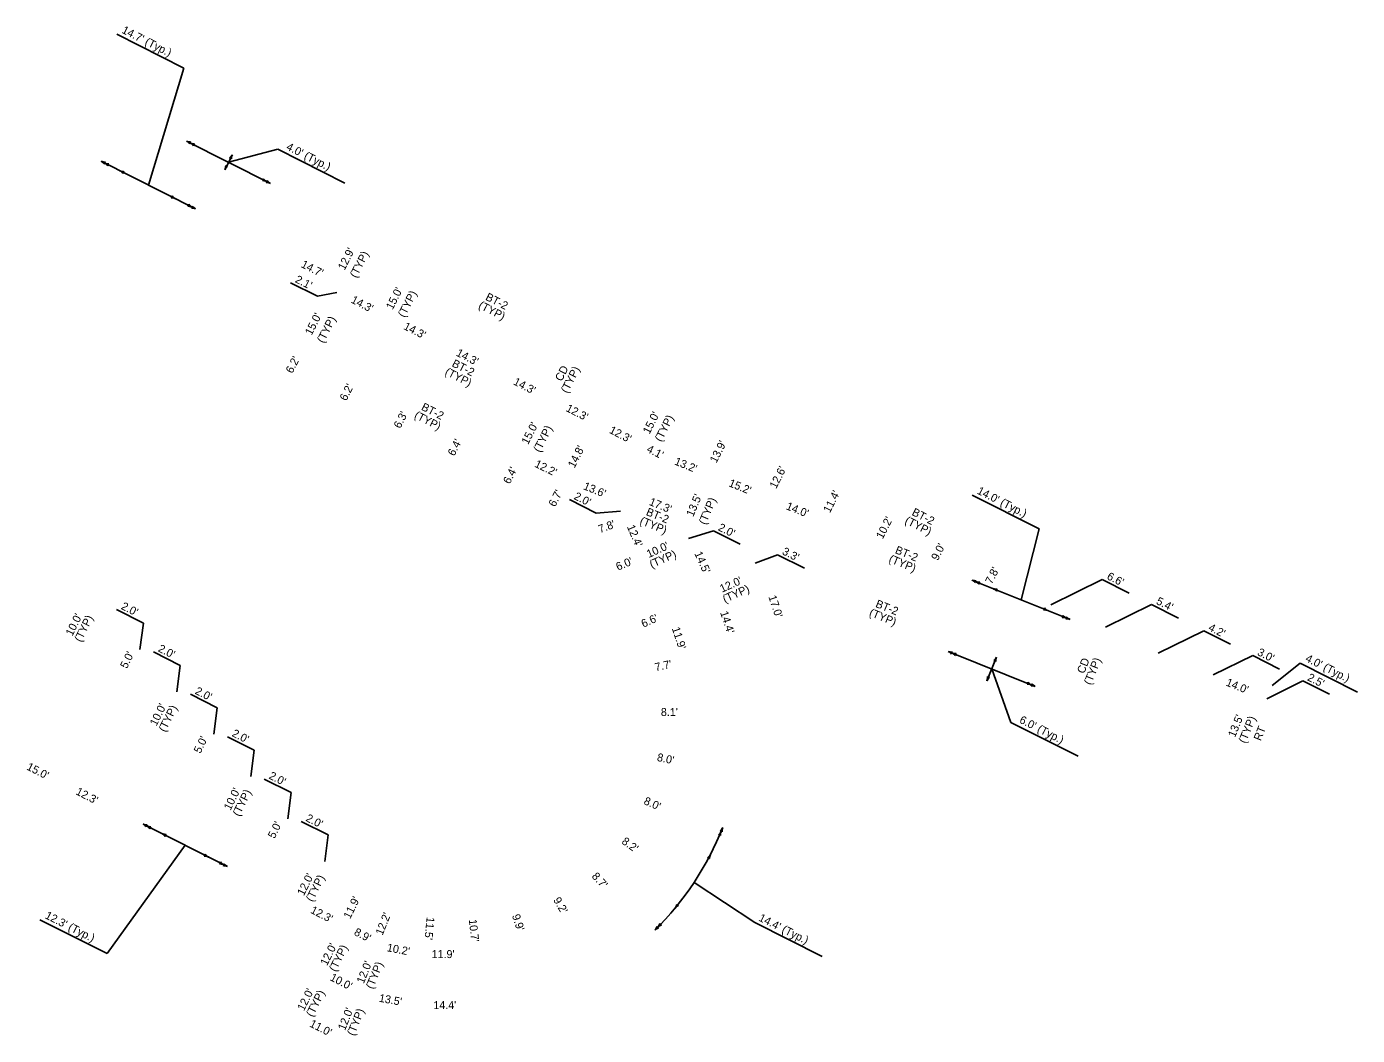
# Model space of a CAD drawing. Extents: x 15558215 to 15558792, y 8787373 to 8787891.
# Drawn here: x 15558477.5 to 15558791.7, y 8787532.3 to 8787770.4 of the extents above; entities that cross this region are included whole.
import ezdxf

# ---------------------------------------------------------------- set-up
doc = ezdxf.new("R2010")
doc.units = 0
doc.layers.add('Draft_Plan_Labels', color=7, linetype='Continuous')
doc.layers.add('Text', color=7, linetype='Continuous')

msp = doc.modelspace()

# ---------------------------------------------------------------- linework, layer by layer
at = {"layer": 'Draft_Plan_Labels'}
for p, q in [((15558515.26, 8787743.4), (15558515.69, 8787743.18)), ((15558515.26, 8787743.4), (15558516.11, 8787742.97)), ((15558516.11, 8787742.97), (15558516.55, 8787742.75)), ((15558516.11, 8787742.97), (15558516.97, 8787742.54)), ((15558526.06, 8787740.19), (15558525.62, 8787739.34)), ((15558526.06, 8787740.19), (15558525.84, 8787739.76)), ((15558495.06, 8787738.66), (15558495.49, 8787738.44)), ((15558495.06, 8787738.66), (15558495.92, 8787738.23)), ((15558495.92, 8787738.23), (15558496.35, 8787738.01)), ((15558495.92, 8787738.23), (15558496.78, 8787737.79)), ((15558524.26, 8787736.62), (15558524.69, 8787737.48)), ((15558524.26, 8787736.62), (15558524.47, 8787737.05)), ((15558499.53, 8787736.41), (15558499.96, 8787736.19)), ((15558499.53, 8787736.41), (15558500.38, 8787735.97)), ((15558534.2, 8787733.85), (15558533.34, 8787734.28)), ((15558534.2, 8787733.85), (15558533.77, 8787734.06)), ((15558535.06, 8787733.41), (15558534.2, 8787733.85)), ((15558535.06, 8787733.41), (15558534.62, 8787733.63)), ((15558512.61, 8787729.81), (15558511.75, 8787730.24)), ((15558512.61, 8787729.81), (15558512.18, 8787730.02)), ((15558516.52, 8787727.83), (15558515.67, 8787728.26)), ((15558516.52, 8787727.83), (15558516.09, 8787728.05)), ((15558517.38, 8787727.4), (15558516.52, 8787727.83)), ((15558517.38, 8787727.4), (15558516.95, 8787727.62)), ((15558700.65, 8787639.79), (15558701.1, 8787639.61)), ((15558700.65, 8787639.79), (15558701.54, 8787639.43)), ((15558701.54, 8787639.43), (15558701.99, 8787639.25)), ((15558701.54, 8787639.43), (15558702.44, 8787639.08)), ((15558705.63, 8787637.8), (15558706.08, 8787637.62)), ((15558705.63, 8787637.8), (15558706.53, 8787637.44)), ((15558718.59, 8787632.61), (15558717.69, 8787632.96)), ((15558718.59, 8787632.61), (15558718.14, 8787632.79)), ((15558722.97, 8787630.85), (15558722.07, 8787631.21)), ((15558722.97, 8787630.85), (15558722.52, 8787631.03)), ((15558723.86, 8787630.49), (15558722.97, 8787630.85)), ((15558723.86, 8787630.49), (15558723.41, 8787630.67)), ((15558695.04, 8787622.96), (15558695.49, 8787622.78)), ((15558695.04, 8787622.96), (15558695.93, 8787622.6)), ((15558695.93, 8787622.6), (15558696.38, 8787622.42)), ((15558695.93, 8787622.6), (15558696.83, 8787622.24)), ((15558706.45, 8787621.62), (15558706.09, 8787620.72)), ((15558706.45, 8787621.62), (15558706.27, 8787621.17)), ((15558704.22, 8787616.05), (15558704.58, 8787616.94)), ((15558704.22, 8787616.05), (15558704.4, 8787616.5)), ((15558714.74, 8787615.06), (15558713.84, 8787615.42)), ((15558714.74, 8787615.06), (15558714.29, 8787615.24)), ((15558715.63, 8787614.71), (15558714.74, 8787615.06)), ((15558715.63, 8787614.71), (15558715.18, 8787614.89)), ((15558504.97, 8787582.22), (15558505.4, 8787582)), ((15558504.97, 8787582.22), (15558505.83, 8787581.79)), ((15558505.83, 8787581.79), (15558506.26, 8787581.57)), ((15558505.83, 8787581.79), (15558506.68, 8787581.35)), ((15558509.43, 8787579.97), (15558509.86, 8787579.75)), ((15558509.43, 8787579.97), (15558510.29, 8787579.54)), ((15558641.47, 8787580.52), (15558641.1, 8787579.64)), ((15558641.47, 8787580.52), (15558641.28, 8787580.08)), ((15558641.83, 8787581.42), (15558641.47, 8787580.52)), ((15558641.83, 8787581.42), (15558641.65, 8787580.97)), ((15558520.41, 8787574.43), (15558519.55, 8787574.86)), ((15558520.41, 8787574.43), (15558519.98, 8787574.65)), ((15558638.94, 8787575.04), (15558638.49, 8787574.19)), ((15558638.94, 8787575.04), (15558638.71, 8787574.61)), ((15558524.01, 8787572.61), (15558523.16, 8787573.04)), ((15558524.01, 8787572.61), (15558523.58, 8787572.83)), ((15558524.87, 8787572.18), (15558524.01, 8787572.61)), ((15558524.87, 8787572.18), (15558524.44, 8787572.4)), ((15558630.52, 8787562.31), (15558631.13, 8787563.05)), ((15558630.52, 8787562.31), (15558630.83, 8787562.69)), ((15558625.79, 8787557.16), (15558626.47, 8787557.83)), ((15558625.79, 8787557.16), (15558626.13, 8787557.5)), ((15558626.47, 8787557.83), (15558627.14, 8787558.52)), ((15558626.47, 8787557.83), (15558626.81, 8787558.18))]:
    msp.add_line(p, q, dxfattribs=at)
for centre, radius, start, end in [((15558514.3, 8787741.51), 2.12, 35.1558, 63.2283), ((15558516.21, 8787745.3), 2.12, 243.2283, 271.3008), ((15558516.85, 8787742.6), 0.821, 135.495, 170.9617), ((15558515.16, 8787741.07), 2.12, 35.1558, 63.2283), ((15558517.07, 8787744.87), 2.12, 243.2283, 271.3008), ((15558517.7, 8787742.17), 0.821, 135.495, 170.9617), ((15558524.16, 8787741.15), 2.12, 305.1559, 333.2283), ((15558527.95, 8787739.24), 2.12, 153.2283, 181.3008), ((15558496.02, 8787740.56), 2.12, 243.2283, 271.3008), ((15558494.1, 8787736.76), 2.12, 35.1558, 63.2283), ((15558496.65, 8787737.86), 0.821, 135.495, 170.9617), ((15558496.88, 8787740.12), 2.12, 243.2283, 271.3008), ((15558494.96, 8787736.33), 2.12, 35.1558, 63.2283), ((15558497.51, 8787737.42), 0.821, 135.495, 170.9617), ((15558522.36, 8787737.58), 2.12, 333.2283, 1.3008), ((15558526.15, 8787735.66), 2.12, 125.1558, 153.2283), ((15558525.06, 8787738.21), 0.821, 225.495, 260.9617), ((15558525.25, 8787738.6), 0.821, 45.495, 80.9617), ((15558500.48, 8787738.3), 2.12, 243.2283, 271.3008), ((15558498.57, 8787734.51), 2.12, 35.1558, 63.2283), ((15558501.12, 8787735.61), 0.821, 135.495, 170.9617), ((15558532.61, 8787734.65), 0.821, 315.495, 350.9617), ((15558533.24, 8787731.95), 2.12, 63.2283, 91.3008), ((15558535.16, 8787735.74), 2.12, 215.1559, 243.2283), ((15558533.47, 8787734.22), 0.821, 315.495, 350.9617), ((15558534.1, 8787731.52), 2.12, 63.2283, 91.3008), ((15558536.01, 8787735.31), 2.12, 215.1559, 243.2283), ((15558511.02, 8787730.61), 0.821, 315.495, 350.9617), ((15558513.57, 8787731.7), 2.12, 215.1559, 243.2283), ((15558511.65, 8787727.91), 2.12, 63.2283, 91.3008), ((15558514.93, 8787728.63), 0.821, 315.495, 350.9617), ((15558515.57, 8787725.93), 2.12, 63.2283, 91.3008), ((15558517.48, 8787729.73), 2.12, 215.1559, 243.2283), ((15558515.79, 8787728.2), 0.821, 315.495, 350.9617), ((15558516.42, 8787725.5), 2.12, 63.2283, 91.3008), ((15558518.34, 8787729.3), 2.12, 215.1559, 243.2283), ((15558701.44, 8787641.76), 2.12, 248.1655, 276.238), ((15558699.86, 8787637.82), 2.12, 40.0931, 68.1655), ((15558702.31, 8787639.13), 0.821, 140.4322, 175.8989), ((15558702.33, 8787641.41), 2.12, 248.1655, 276.238), ((15558700.75, 8787637.46), 2.12, 40.0931, 68.1655), ((15558703.2, 8787638.77), 0.821, 140.4322, 175.8989), ((15558706.42, 8787639.77), 2.12, 248.1655, 276.238), ((15558704.84, 8787635.82), 2.12, 40.0931, 68.1655), ((15558707.29, 8787637.13), 0.821, 140.4322, 175.8989), ((15558716.93, 8787633.27), 0.821, 320.4322, 355.8989), ((15558719.38, 8787634.58), 2.12, 220.0931, 248.1655), ((15558717.8, 8787630.63), 2.12, 68.1655, 96.238), ((15558721.31, 8787631.51), 0.821, 320.4322, 355.8989), ((15558722.18, 8787628.88), 2.12, 68.1655, 96.238), ((15558723.76, 8787632.82), 2.12, 220.0931, 248.1655), ((15558722.2, 8787631.16), 0.821, 320.4322, 355.8989), ((15558723.07, 8787628.52), 2.12, 68.1655, 96.238), ((15558724.65, 8787632.47), 2.12, 220.0931, 248.1655), ((15558694.25, 8787620.98), 2.12, 40.0931, 68.1655), ((15558695.83, 8787624.93), 2.12, 248.1655, 276.238), ((15558696.7, 8787622.29), 0.821, 140.4322, 175.8989), ((15558695.14, 8787620.63), 2.12, 40.0931, 68.1655), ((15558696.72, 8787624.57), 2.12, 248.1655, 276.238), ((15558697.59, 8787621.94), 0.821, 140.4322, 175.8989), ((15558704.48, 8787622.41), 2.12, 310.0931, 338.1655), ((15558705.79, 8787619.96), 0.821, 50.4322, 85.8989), ((15558708.42, 8787620.83), 2.12, 158.1655, 186.238), ((15558702.25, 8787616.84), 2.12, 338.1655, 6.238), ((15558704.88, 8787617.7), 0.821, 230.4322, 265.8989), ((15558706.19, 8787615.26), 2.12, 130.0931, 158.1655), ((15558713.08, 8787615.73), 0.821, 320.4322, 355.8989), ((15558713.95, 8787613.09), 2.12, 68.1655, 96.238), ((15558715.53, 8787617.04), 2.12, 220.0931, 248.1655), ((15558713.97, 8787615.37), 0.821, 320.4322, 355.8989), ((15558714.84, 8787612.73), 2.12, 68.1655, 96.238), ((15558716.42, 8787616.68), 2.12, 220.0931, 248.1655), ((15558505.92, 8787584.12), 2.12, 243.2283, 271.3008), ((15558504.01, 8787580.32), 2.12, 35.1558, 63.2283), ((15558506.56, 8787581.42), 0.821, 135.495, 170.9617), ((15558506.78, 8787583.68), 2.12, 243.2283, 271.3008), ((15558504.87, 8787579.89), 2.12, 35.1558, 63.2283), ((15558507.42, 8787580.98), 0.821, 135.495, 170.9617), ((15558510.39, 8787581.87), 2.12, 243.2283, 271.3008), ((15558508.47, 8787578.07), 2.12, 35.1558, 63.2283), ((15558511.02, 8787579.17), 0.821, 135.495, 170.9617), ((15558639.51, 8787581.34), 2.12, 309.2143, 337.2868), ((15558640.78, 8787578.88), 0.821, 49.5535, 85.0202), ((15558639.86, 8787582.21), 2.12, 309.997, 338.0695), ((15558641.16, 8787579.76), 0.821, 50.3361, 85.8029), ((15558643.43, 8787579.7), 2.12, 157.2868, 185.3593), ((15558643.8, 8787580.62), 2.12, 158.0695, 186.142), ((15558518.82, 8787575.23), 0.821, 315.495, 350.9617), ((15558519.45, 8787572.53), 2.12, 63.2283, 91.3008), ((15558521.37, 8787576.33), 2.12, 215.1559, 243.2283), ((15558522.42, 8787573.41), 0.821, 315.495, 350.9617), ((15558524.97, 8787574.51), 2.12, 215.1559, 243.2283), ((15558637.05, 8787576.03), 2.12, 304.2959, 332.3684), ((15558638.11, 8787573.46), 0.821, 44.6351, 80.1018), ((15558640.82, 8787574.06), 2.12, 152.3684, 180.4409), ((15558523.06, 8787570.71), 2.12, 63.2283, 91.3008), ((15558523.28, 8787572.98), 0.821, 315.495, 350.9617), ((15558523.92, 8787570.28), 2.12, 63.2283, 91.3008), ((15558525.83, 8787574.08), 2.12, 215.1559, 243.2283), ((15558628.88, 8787563.66), 2.12, 320.6974, 348.7699), ((15558632.16, 8787560.96), 2.12, 112.6249, 140.6974), ((15558631.65, 8787563.69), 0.821, 212.964, 248.4307), ((15558624.29, 8787558.66), 2.12, 314.9963, 343.0688), ((15558627.29, 8787555.65), 2.12, 106.9238, 134.9963), ((15558627.05, 8787558.42), 0.821, 207.2629, 242.7296), ((15558624.95, 8787559.32), 2.12, 315.779, 343.8515), ((15558627.99, 8787556.35), 2.12, 107.7065, 135.779), ((15558627.71, 8787559.11), 0.821, 208.0456, 243.5123)]:
    msp.add_arc(centre, radius, start, end, dxfattribs=at)
at = {"layer": 'Text'}
for p, q in [((15558498.75, 8787768.62), (15558514.61, 8787760.62)), ((15558506.22, 8787733.03), (15558514.61, 8787760.62)), ((15558535.06, 8787733.41), (15558515.26, 8787743.4)), ((15558526.06, 8787740.19), (15558524.26, 8787736.62)), ((15558525.16, 8787738.41), (15558536.77, 8787741.48)), ((15558536.77, 8787741.48), (15558552.63, 8787733.48)), ((15558495.06, 8787738.66), (15558517.38, 8787727.4)), ((15558546.13, 8787706.77), (15558539.81, 8787709.96)), ((15558550.7, 8787707.69), (15558546.13, 8787706.77)), ((15558611.95, 8787655.62), (15558605.63, 8787658.81)), ((15558700.68, 8787659.87), (15558716.54, 8787651.87)), ((15558617.72, 8787656.06), (15558611.95, 8787655.62)), ((15558712.26, 8787635.14), (15558716.54, 8787651.87)), ((15558633.74, 8787649.58), (15558639.66, 8787651.43)), ((15558645.98, 8787648.24), (15558639.66, 8787651.43)), ((15558649.46, 8787643.78), (15558654.79, 8787645.77)), ((15558661.11, 8787642.58), (15558654.79, 8787645.77)), ((15558700.65, 8787639.79), (15558723.86, 8787630.49)), ((15558719.26, 8787633.94), (15558731.44, 8787639.9)), ((15558737.76, 8787636.72), (15558731.44, 8787639.9)), ((15558505.04, 8787629.66), (15558498.72, 8787632.85)), ((15558732.18, 8787628.69), (15558743.09, 8787634.03)), ((15558749.41, 8787630.84), (15558743.09, 8787634.03)), ((15558504.25, 8787623.42), (15558505.04, 8787629.66)), ((15558744.65, 8787622.55), (15558755.41, 8787627.81)), ((15558761.73, 8787624.63), (15558755.41, 8787627.81)), ((15558513.76, 8787619.65), (15558507.44, 8787622.84)), ((15558715.63, 8787614.71), (15558695.04, 8787622.96)), ((15558706.45, 8787621.62), (15558704.22, 8787616.05)), ((15558757.59, 8787617.4), (15558766.96, 8787621.98)), ((15558773.28, 8787618.8), (15558766.96, 8787621.98)), ((15558512.97, 8787613.42), (15558513.76, 8787619.65)), ((15558705.34, 8787618.83), (15558709.87, 8787606.2)), ((15558771.52, 8787614.94), (15558778.17, 8787620.17)), ((15558791.67, 8787613.36), (15558778.17, 8787620.17)), ((15558770.25, 8787611.77), (15558778.78, 8787616.02)), ((15558785.1, 8787612.84), (15558778.78, 8787616.02)), ((15558522.48, 8787609.65), (15558516.16, 8787612.84)), ((15558521.69, 8787603.41), (15558522.48, 8787609.65)), ((15558709.87, 8787606.2), (15558725.73, 8787598.2)), ((15558531.2, 8787599.64), (15558524.88, 8787602.83)), ((15558530.41, 8787593.41), (15558531.2, 8787599.64)), ((15558539.92, 8787589.64), (15558533.6, 8787592.83)), ((15558539.13, 8787583.41), (15558539.92, 8787589.64)), ((15558548.64, 8787579.64), (15558542.33, 8787582.82)), ((15558504.97, 8787582.22), (15558524.87, 8787572.18)), ((15558547.86, 8787573.4), (15558548.64, 8787579.64)), ((15558514.92, 8787577.2), (15558496.49, 8787551.64)), ((15558635.07, 8787568.45), (15558649.44, 8787558.95)), ((15558480.63, 8787559.64), (15558496.49, 8787551.64)), ((15558665.3, 8787550.95), (15558649.44, 8787558.95))]:
    msp.add_line(p, q, dxfattribs=at)
msp.add_arc((15558576.39, 8787607.24), 70.35, 314.6039, 338.4617, dxfattribs=at)

# ---------------------------------------------------------------- texts
for s, height, rotation, p in [("14.7' (Typ.)", 1.8898, 333.0592, (15558499.79, 8787769.03)), ("4.0' (Typ.)", 1.8898, 333.0592, (15558538.62, 8787741.48)), ("12.9'", 1.89, 63.0592, (15558552.54, 8787712.79)), ("14.7'", 1.89, 332.9068, (15558542.11, 8787713.74)), ('(TYP)', 1.89, 63.0592, (15558555.36, 8787710.96)), ("2.1'", 1.89, 333.0592, (15558540.72, 8787710.16)), ("15.0'", 1.89, 63.0592, (15558563.88, 8787703.46)), ("14.3'", 1.89, 332.9068, (15558553.9, 8787705.36)), ('(TYP)', 1.89, 63.0592, (15558566.7, 8787701.63)), ('(TYP)', 1.89, 332.9068, (15558583.99, 8787704.07)), ('BT-2', 1.89, 332.9068, (15558585.65, 8787706.02)), ("15.0'", 1.89, 63.0592, (15558544.76, 8787697.42)), ('(TYP)', 1.89, 63.0592, (15558547.58, 8787695.59)), ("14.3'", 1.89, 332.9068, (15558566.31, 8787699.1)), ("6.2'", 1.89, 63.0592, (15558540.22, 8787688.43)), ("14.3'", 1.89, 332.9068, (15558578.73, 8787692.84)), ('(TYP)', 1.89, 332.9068, (15558576.07, 8787688.37)), ('BT-2', 1.89, 332.9068, (15558577.73, 8787690.32)), ('CD', 1.89, 62.7464, (15558603.81, 8787686.55)), ('(TYP)', 1.89, 62.7464, (15558605.17, 8787683.75)), ("6.2'", 1.89, 63.0592, (15558552.95, 8787681.94)), ("14.3'", 1.89, 332.9068, (15558592.23, 8787686.03)), ('BT-2', 1.89, 332.9068, (15558570.49, 8787680.06)), ("12.3'", 1.89, 332.9068, (15558604.64, 8787679.76)), ("6.3'", 1.89, 63.0592, (15558565.7, 8787675.43)), ('(TYP)', 1.89, 332.9068, (15558568.82, 8787678.11)), ("15.0'", 1.89, 63.0592, (15558595.87, 8787671.63)), ("15.0'", 1.89, 63.0592, (15558624.52, 8787674.11)), ('(TYP)', 1.89, 63.0592, (15558627.34, 8787672.28)), ('(TYP)', 1.89, 63.0592, (15558598.69, 8787669.8)), ("12.3'", 1.89, 332.9068, (15558614.87, 8787674.6)), ("6.4'", 1.89, 63.0592, (15558578.46, 8787668.92)), ("14.8'", 1.89, 63.0592, (15558606.83, 8787666.11)), ("4.1'", 1.89, 332.9068, (15558623.7, 8787670.14)), ("13.9'", 1.89, 63.0592, (15558640.33, 8787667.28)), ("12.2'", 1.89, 334.1194, (15558597.24, 8787666.6)), ("13.2'", 1.89, 338.1655, (15558630.28, 8787667.11)), ("6.4'", 1.89, 63.0592, (15558591.54, 8787662.32)), ("12.6'", 1.89, 63.0592, (15558654.45, 8787661.22)), ("6.7'", 1.89, 63.0592, (15558602.25, 8787656.92)), ("13.6'", 1.89, 337.7392, (15558608.76, 8787661.28)), ("15.2'", 1.89, 338.1655, (15558643.08, 8787661.98)), ("11.4'", 1.89, 63.0592, (15558667.13, 8787655.51)), ("14.0' (Typ.)", 1.8898, 333.0592, (15558701.72, 8787660.28)), ("2.0'", 1.89, 333.0592, (15558606.54, 8787659)), ("17.3'", 1.89, 337.844, (15558624.29, 8787657.58)), ("13.5'", 1.89, 67.2802, (15558634.86, 8787654.61)), ('(TYP)', 1.89, 67.2802, (15558637.8, 8787652.72)), ("14.0'", 1.89, 338.1655, (15558656.63, 8787656.55)), ('BT-2', 1.89, 337.844, (15558623.57, 8787655.19)), ("10.2'", 1.89, 63.0592, (15558679.59, 8787649.34)), ('(TYP)', 1.89, 332.9068, (15558684.65, 8787653.28)), ('BT-2', 1.89, 332.9068, (15558686.32, 8787655.23)), ("7.8'", 1.89, 20.4831, (15558612.86, 8787650.85)), ("12.4'", 1.89, 293.0649, (15558619.17, 8787652.39)), ('(TYP)', 1.89, 337.844, (15558622.08, 8787653.1)), ("2.0'", 1.89, 333.0592, (15558640.57, 8787651.63)), ("10.0'", 1.89, 24.1758, (15558624.37, 8787644.99)), ("9.0'", 1.89, 63.0592, (15558692.61, 8787644.27)), ('(TYP)', 1.89, 24.1758, (15558625.06, 8787642.56)), ("14.5'", 1.89, 294.176, (15558635.1, 8787646.07)), ("3.3'", 1.89, 333.0592, (15558655.7, 8787645.97)), ('(TYP)', 1.89, 337.844, (15558680.88, 8787644.11)), ('BT-2', 1.89, 337.844, (15558682.37, 8787646.19)), ("6.0'", 1.89, 23.0649, (15558617.09, 8787641.98)), ("7.8'", 1.89, 63.0592, (15558705.36, 8787638.68)), ("12.0'", 1.89, 24.176, (15558641.64, 8787636.79)), ("6.6'", 1.89, 333.0592, (15558732.36, 8787640.1)), ('(TYP)', 1.89, 24.176, (15558642.33, 8787634.37)), ("17.0'", 1.89, 288.1488, (15558652.59, 8787635.88)), ("2.0'", 1.89, 333.0592, (15558499.63, 8787633.04)), ('(TYP)', 1.89, 337.844, (15558676.24, 8787631.42)), ('BT-2', 1.89, 337.844, (15558677.74, 8787633.5)), ("5.4'", 1.89, 333.0592, (15558744, 8787634.23)), ("10.0'", 1.89, 63.7103, (15558488.27, 8787626.45)), ('(TYP)', 1.89, 63.7103, (15558490.34, 8787625.02)), ("6.6'", 1.89, 24.176, (15558623.1, 8787628.53)), ("14.4'", 1.89, 288.1488, (15558641.19, 8787632.14)), ("11.9'", 1.89, 288.1488, (15558629.79, 8787628.4)), ("4.2'", 1.89, 333.0592, (15558756.32, 8787628.01)), ("2.0'", 1.89, 333.0592, (15558508.35, 8787623.04)), ("3.0'", 1.89, 333.0592, (15558767.88, 8787622.18)), ("5.0'", 1.89, 63.7103, (15558501.14, 8787618.75)), ("7.7'", 1.89, 12.1806, (15558626.02, 8787618.27)), ('CD', 1.89, 68.1655, (15558727.14, 8787617.56)), ('(TYP)', 1.89, 68.1655, (15558728.76, 8787614.9)), ("4.0' (Typ.)", 1.8898, 333.2283, (15558779.22, 8787620.72)), ("2.5'", 1.89, 333.0592, (15558779.69, 8787616.22)), ("2.0'", 1.89, 333.0592, (15558517.08, 8787613.03)), ("14.0'", 1.89, 338.1655, (15558760.47, 8787614.94)), ("10.0'", 1.89, 63.7103, (15558508.14, 8787605.22)), ('(TYP)', 1.89, 63.7103, (15558510.21, 8787603.79)), ("8.1'", 1.89, 0.1852, (15558627.23, 8787607.71)), ("6.0' (Typ.)", 1.8898, 333.0592, (15558711.71, 8787606.21)), ("13.5'", 1.89, 67.9964, (15558762.78, 8787602.53)), ("2.0'", 1.89, 333.0592, (15558525.8, 8787603.03)), ('(TYP)', 1.89, 67.9964, (15558765.27, 8787601.13)), ('RT', 1.89, 68.1655, (15558768.84, 8787601.71)), ("5.0'", 1.89, 63.7103, (15558518.51, 8787598.74)), ("8.0'", 1.89, 348.1898, (15558626.21, 8787597.14)), ("15.0'", 1.89, 332.9068, (15558477.31, 8787595.15)), ("2.0'", 1.89, 333.0592, (15558534.52, 8787593.03)), ("12.3'", 1.89, 332.9068, (15558488.92, 8787589.3)), ("10.0'", 1.89, 63.7103, (15558525.61, 8787585.31)), ('(TYP)', 1.89, 63.7103, (15558527.68, 8787583.88)), ("8.0'", 1.89, 336.1944, (15558623.02, 8787587)), ("5.0'", 1.89, 63.7103, (15558536.01, 8787578.64)), ("2.0'", 1.89, 333.0592, (15558543.24, 8787583.02)), ("8.2'", 1.89, 324.1989, (15558617.8, 8787577.75)), ("12.0'", 1.89, 63.7103, (15558542.93, 8787565.15)), ('(TYP)', 1.89, 63.7103, (15558545, 8787563.72)), ("8.7'", 1.89, 312.2035, (15558610.77, 8787569.79)), ("11.9'", 1.89, 63.7103, (15558553.86, 8787559.67)), ("9.2'", 1.89, 300.2081, (15558601.74, 8787564.3)), ("12.3' (Typ.)", 1.8898, 333.0592, (15558481.67, 8787560.05)), ("12.3'", 1.89, 332.9068, (15558544.34, 8787561.32)), ("12.2'", 1.89, 68.1206, (15558561.51, 8787555.82)), ("9.9'", 1.89, 288.2127, (15558592.05, 8787560.61)), ("14.4' (Typ.)", 1.8898, 333.3975, (15558650.14, 8787559.48)), ("8.9'", 1.89, 332.9068, (15558554.62, 8787556.13)), ("11.5'", 1.89, 264.2218, (15558571.95, 8787560.35)), ("10.7'", 1.89, 276.2172, (15558581.88, 8787559.66)), ("12.0'", 1.89, 63.7103, (15558548.4, 8787548.64)), ('(TYP)', 1.89, 63.7103, (15558550.47, 8787547.21)), ("10.2'", 1.89, 349.2786, (15558562.43, 8787552.21)), ("11.9'", 1.89, 0.19, (15558573.1, 8787550.56)), ("12.0'", 1.89, 68.1206, (15558557.06, 8787544.4)), ('(TYP)', 1.89, 68.1206, (15558559.24, 8787543.13)), ("10.0'", 1.89, 332.9068, (15558548.94, 8787545.42)), ("12.0'", 1.89, 63.7103, (15558542.97, 8787537.97)), ('(TYP)', 1.89, 63.7103, (15558545.04, 8787536.54)), ("13.5'", 1.89, 349.5903, (15558560.56, 8787540.3)), ("12.0'", 1.89, 68.1206, (15558552.64, 8787533.36)), ("14.4'", 1.89, 0.5017, (15558573.52, 8787538.52)), ("11.0'", 1.89, 332.9068, (15558544.12, 8787534.51)), ('(TYP)', 1.89, 68.1206, (15558554.81, 8787532.09))]:
    msp.add_text(s, height=height, rotation=rotation, dxfattribs=at).set_placement(p)

doc.saveas('drawing.dxf')
